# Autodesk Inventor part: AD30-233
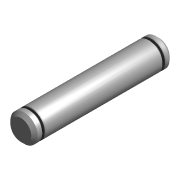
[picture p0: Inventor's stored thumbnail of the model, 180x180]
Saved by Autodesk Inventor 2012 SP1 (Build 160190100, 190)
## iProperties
Shininess: 0.0
Length Units: 11269
Angle Units: 11279
Time Units: 11290
Mass Units: 11283
Length Display Precision: 3
Angle Display Precision: 2
Compacted: True
Created: 2000-06
Part Number: AD30-233
Project: BONDING PRESS
Description: PIVOT SHAFT
Document SubType Name: Modeling
Designer: Ron
Density: 1 g/cm^3
Material: Default
Density: 0.0
Volumn: 0.0
Area: 0.0
PropertySet Name: Model Information
Control State: 0
Master: False
Checked Out: False
Author: Ron
Revision Number: A
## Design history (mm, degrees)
node "Extrusion1" dims "d1" = 64, "d2" = 0
  sketch "Sketch1"
    geometry: C1 r 6.325 at (0, 0); 1 further point
    constraints: 1 centre point, 1 coincident
    dimensions: "d0" = 12.6492 diameter of C1
node "Revolution1" dims "d6" = 90 deg
  sketch "Sketch2"
    geometry: L1 (5.029, 27.25)-(6.325, 27.25); L2 (6.325, 27.25)-(6.325, 28.418); L3 (6.325, 28.418)-(5.029, 28.418); L4 (5.029, 28.418)-(5.029, 27.25); L5 (5.029, -28.418)-(6.325, -28.418); L6 (6.325, -28.418)-(6.325, -27.25); L7 (6.325, -27.25)-(5.029, -27.25); L8 (5.029, -27.25)-(5.029, -28.418); L9 (-6.325, 32)-(6.325, 32) reference; L10 (6.325, -32)-(-6.325, -32) reference; L11 (0, -44.8)-(0, 44.8) reference; L12 (6.325, 28.418)-(6.325, 32); L13 (6.325, -28.418)-(6.325, -32); 1 other entity
    constraints: 20 end point, 4 parallel, 4 vertical, 3 collinear, 2 horizontal, 2 perpendicular, 1 other
    dimensions: "d3" = 1.1684 distance between parallel lines of L1 L3; "d4" = 54.5 distance between parallel lines of L7 L1; "d5" = 10.0584 diameter of L4 L11
node "Chamfer1" dims "d7" = 1.5, "d8" = 1.5, "d9" = 45 deg
body "Solid1"
